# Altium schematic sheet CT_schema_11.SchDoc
size 147 x 119 mm
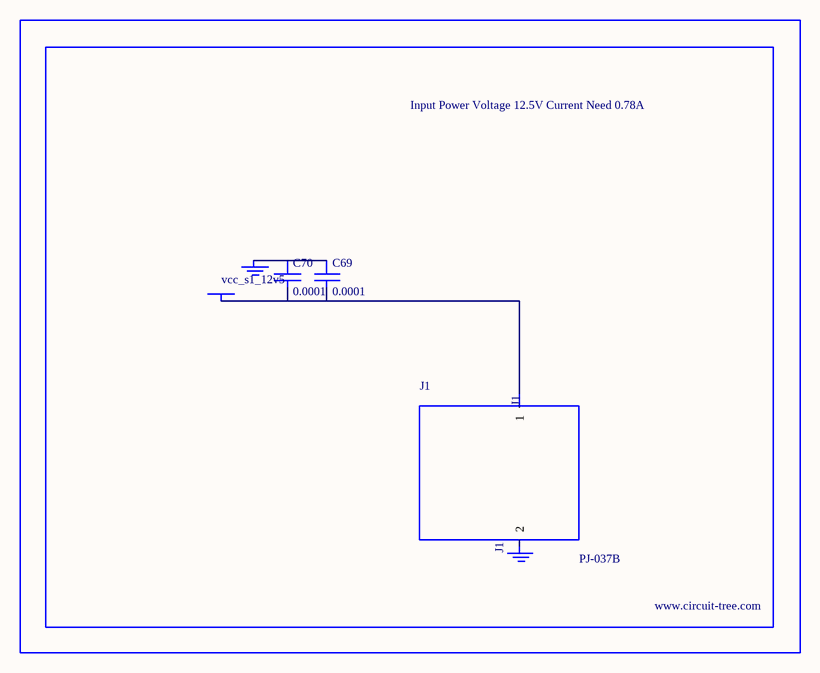
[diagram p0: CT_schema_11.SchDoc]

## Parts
BORDER10  (no value)
C69  0.0001  [EXV-9H]
C70  0.0001  [EXV-9H]
GND_INSTANCE_10_0  (no value)
GND_INSTANCE_10_1  (no value)
J1  PJ-037B  [PJ-037B_PACKAGE]
POWER_INSTANCE_10_0  vcc_s1_12v5

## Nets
NetC69_1: C69.1 C70.1 GND_INSTANCE_10_0.0(GND)
NetC69_2: C69.2 C70.2 J1.1 POWER_INSTANCE_10_0.0(PWR)

Not connected (* = marked no-connect by the designer): GND_INSTANCE_10_1 0(GND); J1 2

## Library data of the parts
BORDER10 = BORDER_PAGE10
C69 C70 = EDK107M035A9HAA
GND_INSTANCE_10_0 GND_INSTANCE_10_1 = GND
POWER_INSTANCE_10_0 = PWR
